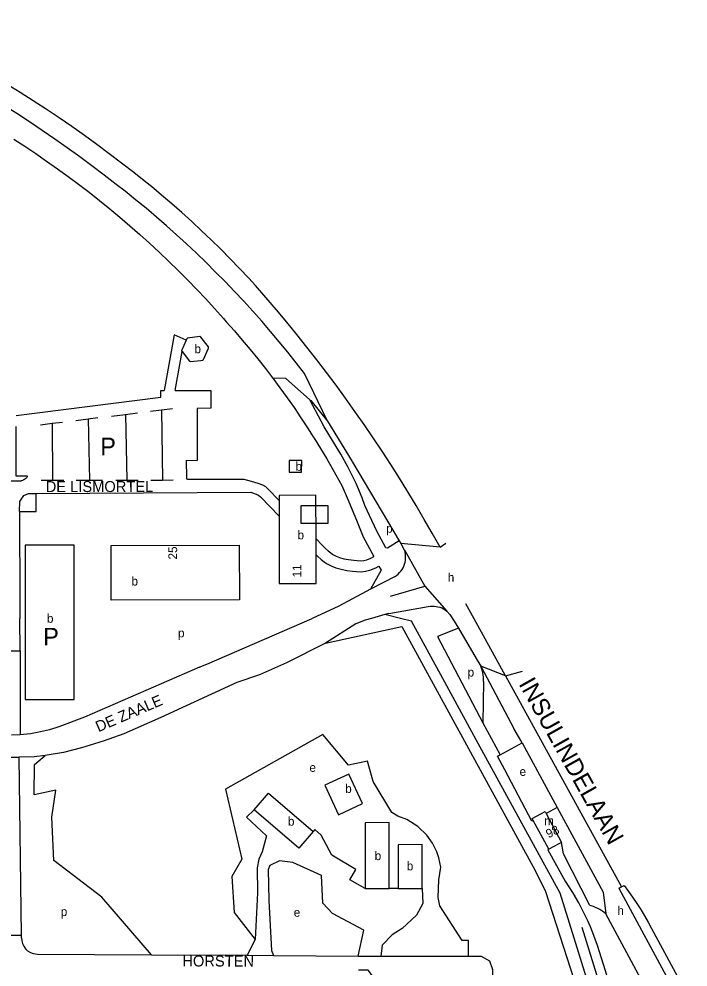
# Model space of a CAD drawing. Extents: x 161494 to 163033, y 383688 to 384862.
# Drawn here: x 162517.1 to 162822.2, y 384341 to 384773.4 of the extents above; entities that cross this region are included whole.
import ezdxf

# ---------------------------------------------------------------- set-up
doc = ezdxf.new("R2010")
doc.units = 0
for name, color, linetype in [('BLT_Basislijn', 7, 'Continuous'), ('BLT_Bebouwing', 7, 'Continuous'), ('BLT_Centroide', 7, 'Continuous'), ('BLT_Huisnummer', 7, 'Continuous'), ('BLT_Plantopo', 7, 'Continuous'), ('BLT_Straatnaam', 7, 'Continuous'), ('BLT_Straatnaam_hoofdweg', 7, 'Continuous'), ('BLT_Tekst_parkeren', 7, 'Continuous'), ('BLT_Vlakafsluiter', 7, 'Continuous')]:
    doc.layers.add(name, color=color, linetype=linetype)

msp = doc.modelspace()

# ---------------------------------------------------------------- linework, layer by layer
at = {"layer": 'BLT_Basislijn'}
for p, q in [((162588.39, 384603.9), (162591.56, 384621.65)), ((162548.66, 384591), (162553.14, 384591.55)), ((162559.35, 384592.25), (162565.71, 384593.05)), ((162565.71, 384593.05), (162571.08, 384593.73)), ((162565.71, 384593.05), (162566.34, 384563.01)), ((162577.06, 384594.54), (162582.13, 384595.16)), ((162582.13, 384595.16), (162587.09, 384595.78)), ((162582.13, 384595.16), (162582.49, 384563.09)), ((162598.34, 384595.79), (162598.3, 384572.07)), ((162526.96, 384588.34), (162532.3, 384588.99)), ((162532.3, 384588.99), (162536.99, 384589.56)), ((162532.3, 384588.99), (162532.44, 384563.05)), ((162542.97, 384590.29), (162548.66, 384591)), ((162548.66, 384591), (162549.3, 384563.04)), ((162593.29, 384572.1), (162598.3, 384572.07)), ((162669.14, 384571.31), (162690.46, 384535.35)), ((162507.72, 384562.68), (162518.08, 384562.69)), ((162527.19, 384563.05), (162532.44, 384563.05)), ((162532.44, 384563.05), (162537.56, 384563.05)), ((162543.14, 384563.08), (162549.3, 384563.04)), ((162549.3, 384563.04), (162555.16, 384563.01)), ((162561.27, 384563.01), (162566.34, 384563.01)), ((162566.34, 384563.01), (162571.43, 384563.01)), ((162577.25, 384563.05), (162582.49, 384563.09)), ((162582.49, 384563.09), (162587.36, 384563.13)), ((162524.88, 384548.71), (162525, 384556.96)), ((162525, 384556.96), (162622.83, 384557.57)), ((162517.3, 384548.79), (162517.44, 384506.82)), ((162517.3, 384548.79), (162524.88, 384548.71)), ((162690.46, 384535.35), (162691.19, 384534.12)), ((162691.19, 384534.12), (162692.78, 384531.3)), ((162692.97, 384530.95), (162692.78, 384531.3)), ((162681.26, 384523.86), (162682.27, 384521.96)), ((162682.27, 384521.96), (162677.42, 384513.27)), ((162688.57, 384519.15), (162677.42, 384513.27)), ((162686.51, 384510.13), (162702.14, 384514.65)), ((162685.79, 384502.29), (162703.72, 384505.35)), ((162720.72, 384506.85), (162724.49, 384500)), ((162683.94, 384501.76), (162677.81, 384500)), ((162685.79, 384502.29), (162683.94, 384501.76)), ((162691.05, 384500), (162683.94, 384501.76)), ((162517.59, 384485.2), (162517.49, 384500)), ((162602.74, 384479.15), (162650.78, 384500)), ((162715.53, 384498.75), (162717.52, 384495.46)), ((162724.49, 384500), (162738.85, 384473.88)), ((162717.52, 384495.46), (162725.62, 384481.73)), ((162513.58, 384485.17), (162517.59, 384485.2)), ((162517.59, 384485.2), (162517.63, 384479.78)), ((162725.62, 384481.73), (162727.64, 384478.27)), ((162728.85, 384471.16), (162728.66, 384452.39)), ((162738.88, 384473.81), (162791.81, 384377.54)), ((162728.66, 384452.39), (162736.51, 384437.72)), ((162746.55, 384443.2), (162742.79, 384449.7)), ((162517.68, 384446.82), (162513.64, 384446.73)), ((162736.51, 384437.72), (162746.55, 384443.2)), ((162746.55, 384443.2), (162762.48, 384413.72)), ((162513.36, 384436.68), (162517.26, 384436.66)), ((162518.24, 384355.54), (162517.26, 384436.66)), ((162735.34, 384437.08), (162736.51, 384437.72)), ((162762.48, 384413.72), (162757.45, 384411.02)), ((162762.48, 384413.72), (162783.47, 384375.18)), ((162689.99, 384376.81), (162685.95, 384376.8)), ((162790.57, 384376.9), (162791.81, 384377.54)), ((162790.57, 384376.9), (162816.4, 384329.35)), ((162791.81, 384377.54), (162792.98, 384378.13)), ((162625.92, 384374.81), (162624.81, 384353.52)), ((162782.73, 384330.75), (162773.92, 384358.94)), ((162513.52, 384355.52), (162518.24, 384355.54)), ((162518.25, 384354.37), (162518.24, 384355.54)), ((162806.45, 384356.92), (162822.17, 384327.78)), ((162624.81, 384353.52), (162621.15, 384346.35)), ((162577.48, 384346.57), (162621.15, 384346.35)), ((162621.15, 384346.35), (162633.1, 384346.29)), ((162633.1, 384346.29), (162671.79, 384345.91)), ((162671.79, 384345.91), (162682.06, 384345.95)), ((162682.06, 384345.95), (162722.09, 384345.95)), ((162806.68, 384268.74), (162781.81, 384347.94))]:
    msp.add_line(p, q, dxfattribs=at)
for points in [[(162561.45, 384697.94), (162555.95, 384702.2), (162550.4, 384706.41), (162544.8, 384710.54), (162539.16, 384714.61), (162533.47, 384718.62), (162527.73, 384722.56), (162521.95, 384726.44), (162516.12, 384730.25), (162510.25, 384733.99), (162504.34, 384737.66), (162498.38, 384741.27), (162492.39, 384744.8), (162486.35, 384748.27), (162480.28, 384751.67), (162474.16, 384755), (162468.01, 384758.25), (162461.82, 384761.44), (162455.6, 384764.56), (162449.34, 384767.6), (162443.04, 384770.57), (162436.9, 384773.39)], [(162575, 384698.98), (162569.49, 384703.36), (162563.92, 384707.67), (162558.3, 384711.92), (162552.64, 384716.11), (162546.93, 384720.23), (162541.17, 384724.28), (162535.37, 384728.27), (162529.52, 384732.19), (162523.63, 384736.05), (162517.69, 384739.84), (162511.71, 384743.56)], [(162514.7, 384718.57), (162519.75, 384715.3), (162524.75, 384711.97), (162529.71, 384708.57), (162534.62, 384705.1), (162539.49, 384701.57), (162544.31, 384697.98), (162549.08, 384694.32), (162553.8, 384690.6), (162558.47, 384686.82), (162563.09, 384682.97), (162567.66, 384679.06), (162572.17, 384675.1), (162576.64, 384671.07), (162581.05, 384666.98), (162585.4, 384662.84), (162589.7, 384658.64), (162593.94, 384654.38), (162598.13, 384650.06), (162602.26, 384645.69), (162606.33, 384641.27), (162610.34, 384636.79), (162611.65, 384635.29)], [(162647.27, 384611.72), (162643.5, 384616.57), (162639.66, 384621.38), (162635.76, 384626.14), (162631.8, 384630.84), (162627.78, 384635.49), (162623.7, 384640.1), (162619.56, 384644.64), (162615.36, 384649.14), (162611.1, 384653.58), (162606.79, 384657.96), (162602.42, 384662.29), (162597.99, 384666.55), (162593.51, 384670.77), (162588.97, 384674.92), (162584.38, 384679.01), (162579.74, 384683.04), (162575.04, 384687.02), (162570.29, 384690.93), (162565.5, 384694.78), (162561.45, 384697.94)], [(162621.91, 384655.18), (162617.71, 384659.61), (162613.46, 384664), (162609.15, 384668.32), (162604.79, 384672.59), (162600.37, 384676.8), (162595.89, 384680.96), (162591.36, 384685.05), (162586.78, 384689.09), (162582.14, 384693.06), (162577.46, 384696.98), (162575, 384698.98)], [(162709.11, 384532.44), (162705.54, 384538.83), (162701.89, 384545.17), (162698.18, 384551.48), (162694.4, 384557.74), (162690.55, 384563.96), (162686.63, 384570.14), (162682.64, 384576.28), (162678.59, 384582.37), (162674.47, 384588.42), (162670.28, 384594.42), (162666.03, 384600.38), (162661.71, 384606.29), (162657.34, 384612.15), (162652.89, 384617.96), (162648.39, 384623.73), (162643.82, 384629.44), (162639.18, 384635.11), (162634.49, 384640.72), (162629.73, 384646.28), (162624.92, 384651.79), (162621.91, 384655.18)], [(162611.65, 384635.29), (162615.34, 384631.14), (162618.95, 384626.93), (162622.51, 384622.68), (162626.01, 384618.37), (162629.44, 384614.02), (162632.71, 384609.74)], [(162593.35, 384626.91), (162587.85, 384629.26), (162583.3, 384603.87)], [(162632.71, 384609.74), (162632.81, 384609.61), (162636.12, 384605.16), (162639.36, 384600.66), (162642.54, 384596.11), (162645.65, 384591.52), (162648.7, 384586.88), (162651.25, 384582.86)], [(162632.71, 384609.74), (162638.57, 384609.55), (162649.74, 384599.72)], [(162515.79, 384592.53), (162581.83, 384600.89), (162581.84, 384603.86), (162583.3, 384603.87)], [(162588.39, 384603.9), (162604.57, 384603.98), (162604.61, 384595.82), (162598.34, 384595.79)], [(162649.74, 384599.72), (162650.12, 384599.36), (162657.84, 384589.97)], [(162690.46, 384535.35), (162685.14, 384531.98), (162684.44, 384532.15), (162680.27, 384539.79), (162676.88, 384546.97), (162674.87, 384551.46), (162673.55, 384555.02), (162670.87, 384561.48), (162667.09, 384569.08), (162663.81, 384574.84), (162656.19, 384587.32), (162649.74, 384599.72)], [(162520.96, 384564.8), (162515.82, 384564.86), (162515.8, 384587.51)], [(162657.84, 384589.97), (162669, 384571.6), (162669.14, 384571.31)], [(162651.25, 384582.86), (162651.67, 384582.2), (162654.58, 384577.48), (162657.43, 384572.71), (162660.2, 384567.91), (162662.9, 384563.06), (162664.27, 384560.54)], [(162593.29, 384572.1), (162593.42, 384564.05), (162593.45, 384563.84), (162593.54, 384563.71), (162593.72, 384563.57), (162593.97, 384563.46), (162594.29, 384563.44), (162619.65, 384563.44), (162622.92, 384562.56), (162626.04, 384561.71)], [(162520.96, 384564.8), (162520.63, 384564.31), (162520.24, 384563.86), (162519.79, 384563.48), (162519.29, 384563.15), (162518.76, 384562.9), (162518.19, 384562.72), (162518.08, 384562.69)], [(162626.04, 384561.71), (162628.2, 384560.89), (162629.58, 384560.07), (162630.78, 384558.91), (162635.71, 384553.78)], [(162517.3, 384548.79), (162517.55, 384553.35), (162519.39, 384556.02), (162521.5, 384556.9), (162525, 384556.96)], [(162622.83, 384557.57), (162626.02, 384556.37), (162626.52, 384556.07), (162627.24, 384555.38), (162635.7, 384546.58)], [(162664.27, 384560.54), (162667.14, 384553.92), (162671.31, 384544.02), (162674.09, 384537.24), (162678.9, 384528.27)], [(162652.56, 384536.24), (162655.22, 384533.48), (162656.75, 384531.95), (162658.05, 384530.76), (162659.24, 384529.87), (162660.23, 384529.17), (162661.77, 384528.38), (162663.2, 384527.8), (162665.19, 384527.23), (162667.41, 384526.78), (162669.74, 384526.49), (162671.34, 384526.35), (162672.85, 384526.29), (162674.31, 384526.47), (162675.66, 384526.77), (162677.6, 384527.52), (162678.9, 384528.27)], [(162652.57, 384529.05), (162653.29, 384528.34), (162654.86, 384526.9), (162656.3, 384525.83), (162657.63, 384524.88), (162659.69, 384523.83), (162661.56, 384523.07), (162663.99, 384522.37), (162666.6, 384521.84), (162669.21, 384521.52), (162671.04, 384521.35), (162673.07, 384521.28), (162675.16, 384521.54), (162677.11, 384521.97), (162679.76, 384522.99), (162681.26, 384523.86)], [(162688.57, 384519.15), (162689.32, 384519.65), (162690.02, 384520.22), (162690.66, 384520.85), (162691.25, 384521.54), (162691.77, 384522.27), (162692.23, 384523.05), (162692.61, 384523.86), (162692.92, 384524.71), (162693.16, 384525.58), (162693.32, 384526.46), (162693.39, 384527.36), (162693.39, 384528.26), (162693.31, 384529.16), (162693.15, 384530.05), (162692.97, 384530.95)], [(162677.42, 384513.27), (162662.88, 384505.61), (162650.78, 384500)], [(162517.44, 384506.82), (162517.45, 384506.17), (162517.49, 384500)], [(162703.72, 384505.35), (162704.6, 384505.51), (162705.49, 384505.58), (162706.38, 384505.57), (162707.27, 384505.49), (162708.15, 384505.32), (162709.01, 384505.08), (162709.84, 384504.76), (162710.65, 384504.37), (162711.41, 384503.91), (162712.18, 384503.33)], [(162712.18, 384503.33), (162713.5, 384501.84), (162715.53, 384498.75)], [(162677.81, 384500), (162674.97, 384499.18), (162670.74, 384497.44), (162656.92, 384488.75)], [(162711.25, 384470.88), (162696.06, 384498.76), (162691.05, 384500)], [(162656.92, 384488.75), (162691.6, 384496.32), (162752.47, 384384.97), (162757.12, 384375.47), (162784.76, 384290.27), (162786.79, 384281.41), (162786.93, 384272.34), (162783.57, 384261.18), (162776.08, 384247.54), (162769.02, 384241.88), (162719.16, 384209.03), (162687.54, 384192.14), (162663.49, 384183.13)], [(162717.52, 384495.46), (162708.01, 384491.71), (162728.66, 384452.39)], [(162656.92, 384488.75), (162639.14, 384479.68), (162626.76, 384474.18), (162616.45, 384470.81), (162581.79, 384454.74), (162564.86, 384447.34), (162555.52, 384444.02), (162545.58, 384440.95), (162537.38, 384438.89), (162529.12, 384437.43)], [(162517.63, 384479.78), (162517.63, 384479.22), (162517.68, 384446.82)], [(162599.49, 384477.77), (162600, 384477.98), (162602.74, 384479.15)], [(162599.49, 384477.77), (162547.05, 384454.9), (162535.32, 384450.47), (162531.09, 384449.23), (162526.91, 384448.21), (162522.4, 384447.4), (162517.68, 384446.82)], [(162728.85, 384471.16), (162728.91, 384472.2), (162728.89, 384473.24), (162728.8, 384474.28), (162728.62, 384475.31), (162728.36, 384476.32), (162728.03, 384477.31), (162727.64, 384478.27)], [(162726.44, 384443), (162711.25, 384470.88)], [(162687.13, 384411.5), (162678.58, 384425.6), (162675.99, 384434.91), (162667.39, 384433.12), (162655.65, 384447.06), (162611.31, 384422.13), (162618.71, 384390.13), (162614.23, 384382.33), (162615.23, 384365.84), (162624.81, 384353.52)], [(162777.96, 384329.25), (162763.82, 384374.63), (162726.44, 384443)], [(162529.12, 384437.43), (162524, 384436.92), (162517.26, 384436.66)], [(162577.48, 384346.57), (162554.94, 384372.87), (162532.95, 384389.62), (162532.11, 384409.39), (162533.9, 384421.65), (162524.01, 384419.53), (162524.13, 384433.32), (162529.12, 384437.43)], [(162751.58, 384407.86), (162751.02, 384407.57), (162738.59, 384430.96), (162735.34, 384437.08)], [(162624.31, 384412.68), (162620.91, 384409.26), (162629.97, 384400.86), (162628.03, 384393.55)], [(162709.38, 384386.48), (162708.54, 384390.78), (162707.6, 384393.55), (162705.65, 384397.49), (162703.11, 384401.06), (162698.91, 384405.12), (162693.95, 384408.2), (162689.86, 384409.79), (162687.13, 384411.5)], [(162674.94, 384376.78), (162667.98, 384380.71), (162670.68, 384385.52), (162659.77, 384392.03), (162654.82, 384401.07), (162652.02, 384403.64), (162651.28, 384402.79)], [(162777.45, 384368.99), (162765.43, 384392.66), (162764.52, 384397.85)], [(162628.03, 384393.55), (162626.41, 384390.25), (162625.74, 384386.22), (162625.92, 384374.81)], [(162758.65, 384394.67), (162758.26, 384394.46), (162766.19, 384380.11), (162770.56, 384373.37)], [(162671.79, 384345.91), (162674.39, 384357.76), (162660.11, 384365.44), (162655.59, 384370.17), (162655.02, 384382.71), (162641.95, 384388.7), (162635.84, 384389.41), (162631.45, 384387.33), (162630.76, 384385.43), (162630.97, 384371.31), (162632.19, 384348.5), (162633.1, 384346.29)], [(162719.23, 384353.08), (162708.94, 384368.83), (162708.29, 384372.74), (162708.51, 384380.72), (162709.38, 384386.48)], [(162700.94, 384376.83), (162701.25, 384369.99), (162698.43, 384364.6), (162691.88, 384358.54), (162687.21, 384355.66), (162682.68, 384350.94), (162682.06, 384345.95)], [(162792.98, 384378.13), (162794.98, 384375.47), (162796.91, 384372.77), (162798.78, 384370.02), (162800.58, 384367.22), (162802.32, 384364.38), (162803.98, 384361.51), (162805.58, 384358.59), (162806.45, 384356.92)], [(162781.81, 384347.94), (162780.89, 384350.83), (162779.89, 384353.69), (162778.82, 384356.53), (162777.67, 384359.33), (162776.45, 384362.11), (162775.16, 384364.85), (162773.8, 384367.56), (162772.36, 384370.23), (162770.86, 384372.86), (162770.56, 384373.37)], [(162784.64, 384365.25), (162783.81, 384365.97), (162782.92, 384366.63), (162781.99, 384367.22), (162781.02, 384367.75), (162780.02, 384368.2), (162778.99, 384368.58), (162777.93, 384368.88), (162777.45, 384368.99)], [(162810.34, 384316.89), (162806.99, 384323.74), (162784.64, 384365.25)], [(162518.25, 384354.37), (162518.35, 384352.98), (162518.65, 384351.77), (162519.26, 384350.44), (162520.03, 384349.33), (162520.99, 384348.38), (162522.36, 384347.55), (162523.56, 384347.11), (162525.58, 384346.83), (162577.48, 384346.57)], [(162722.09, 384345.95), (162722.12, 384353.08), (162719.23, 384353.08)], [(162722.09, 384345.95), (162727.84, 384345.96), (162731.62, 384343.88), (162733.05, 384339.81), (162733.14, 384334.84), (162738.07, 384334.83), (162738.03, 384269.99), (162679.07, 384270.05), (162679.11, 384327.6), (162679.27, 384335.75), (162676.27, 384339.62), (162671.85, 384339.62)]]:
    msp.add_lwpolyline(points, dxfattribs=at)
at = {"layer": 'BLT_Bebouwing'}
for p, q in [((162593.35, 384626.91), (162591.27, 384622.04)), ((162591.27, 384622.04), (162591.56, 384621.65)), ((162624.31, 384412.68), (162630.9, 384420.34)), ((162630.9, 384420.34), (162651.28, 384402.79)), ((162644.69, 384395.14), (162624.31, 384412.68)), ((162757.45, 384411.02), (162764.52, 384397.85)), ((162758.65, 384394.67), (162751.58, 384407.86)), ((162651.28, 384402.79), (162644.69, 384395.14)), ((162763.23, 384397.15), (162758.65, 384394.67)), ((162764.52, 384397.85), (162763.23, 384397.15)), ((162674.94, 384376.78), (162685.95, 384376.8)), ((162689.99, 384376.81), (162700.94, 384376.83))]:
    msp.add_line(p, q, dxfattribs=at)
for points in [[(162591.56, 384621.65), (162594.85, 384617.3), (162595.29, 384617.09), (162600, 384617.65), (162600.91, 384617.77), (162601.29, 384618.08), (162603.53, 384623.3), (162603.47, 384623.78), (162600.05, 384628.29), (162599.61, 384628.5), (162593.97, 384627.81), (162593.61, 384627.51), (162593.35, 384626.91)], [(162645.99, 384566.65), (162646.04, 384571.98), (162640.35, 384572.03), (162640.3, 384566.7), (162645.99, 384566.65)], [(162635.71, 384553.78), (162635.7, 384546.58)], [(162652.56, 384536.24), (162652.53, 384556.26), (162635.71, 384556.1)], [(162635.71, 384556.1), (162635.71, 384553.78)], [(162635.7, 384546.58), (162635.67, 384515.89), (162652.59, 384515.92), (162652.57, 384529.05)], [(162652.57, 384529.05), (162652.56, 384536.24)], [(162673.74, 384415.49), (162667.56, 384428.99), (162656.58, 384423.97)], [(162656.58, 384423.97), (162662.78, 384410.45), (162673.74, 384415.49)], [(162751.58, 384407.86), (162751.1, 384408.75), (162756.98, 384411.9), (162757.45, 384411.02)], [(162685.95, 384376.8), (162685.95, 384406.83), (162674.9, 384406.8), (162674.94, 384376.78)], [(162700.94, 384376.83), (162700.9, 384396.8), (162689.96, 384396.75), (162689.99, 384376.81)]]:
    msp.add_lwpolyline(points, dxfattribs=at)
for points in [[(162519.89, 384533.33), (162519.89, 384463), (162542.34, 384463), (162542.34, 384533.33)], [(162559.09, 384533.23), (162617.57, 384533.32), (162617.61, 384508.39), (162559.13, 384508.3)]]:
    msp.add_lwpolyline(points, close=True, dxfattribs=at)
at = {"layer": 'BLT_Plantopo'}
msp.add_lwpolyline([(162645.6, 384551.37), (162645.6, 384543.35), (162658.13, 384543.35), (162658.13, 384551.37)], close=True, dxfattribs=at)
at = {"layer": 'BLT_Vlakafsluiter'}
for p, q in [((162657.84, 384589.97), (162647.27, 384611.72)), ((162709.11, 384532.44), (162691.19, 384534.12)), ((162709.11, 384532.44), (162711.73, 384534.3)), ((162692.97, 384530.95), (162702.14, 384514.65)), ((162702.14, 384514.65), (162712.18, 384503.33)), ((162727.64, 384478.27), (162742.79, 384449.7)), ((162738.88, 384473.81), (162727.64, 384478.27)), ((162738.88, 384473.81), (162746.65, 384475.86)), ((162783.47, 384375.18), (162784.64, 384365.25))]:
    msp.add_line(p, q, dxfattribs=at)

# ---------------------------------------------------------------- texts
at = {"layer": 'BLT_Centroide'}
for s, p in [('b', (162597.14, 384620.95)), ('b', (162643.17, 384567.34)), ('b', (162644.12, 384536.05)), ('p', (162684.49, 384539.05)), ('b', (162568.42, 384514.98)), ('h', (162712.62, 384516.67)), ('b', (162529.86, 384498.01)), ('p', (162589.61, 384491.35)), ('p', (162721.67, 384473.47)), ('e', (162649.55, 384429.99)), ('e', (162745.35, 384428.16)), ('b', (162665.85, 384420.37)), ('b', (162639.74, 384405.46)), ('m', (162756.56, 384405.68)), ('b', (162679.29, 384389.74)), ('b', (162693.92, 384385.09)), ('p', (162536.15, 384364.27)), ('e', (162642.4, 384363.91)), ('h', (162789.94, 384364.71))]:
    msp.add_text(s, height=4, dxfattribs=at).set_placement(p)
at = {"layer": 'BLT_Huisnummer'}
for s, rotation, p in [('25', 89.6507, (162589.2, 384526.85)), ('11', 90.0881, (162645.88, 384518.67)), ('98', 26.0482, (162758.57, 384399.64))]:
    msp.add_text(s, height=4, rotation=rotation, dxfattribs=at).set_placement(p)
at = {"layer": 'BLT_Straatnaam'}
for s, rotation, p in [('DE LISMORTEL', 0.0477, (162529.3, 384557.6)), ('DE ZAALE', 23.1988, (162553.35, 384448.02)), ('HORSTEN', 359.8991, (162591.59, 384341.25))]:
    msp.add_text(s, height=5, rotation=rotation, dxfattribs=at).set_placement(p)
at = {"layer": 'BLT_Straatnaam_hoofdweg'}
msp.add_text('INSULINDELAAN', height=8, rotation=299.2649, dxfattribs=at).set_placement((162744.74, 384470.18))
at = {"layer": 'BLT_Tekst_parkeren'}
for p in [(162554.17, 384574.42), (162528.17, 384487.68)]:
    msp.add_text('P', height=8, dxfattribs=at).set_placement(p)

doc.saveas('drawing.dxf')
